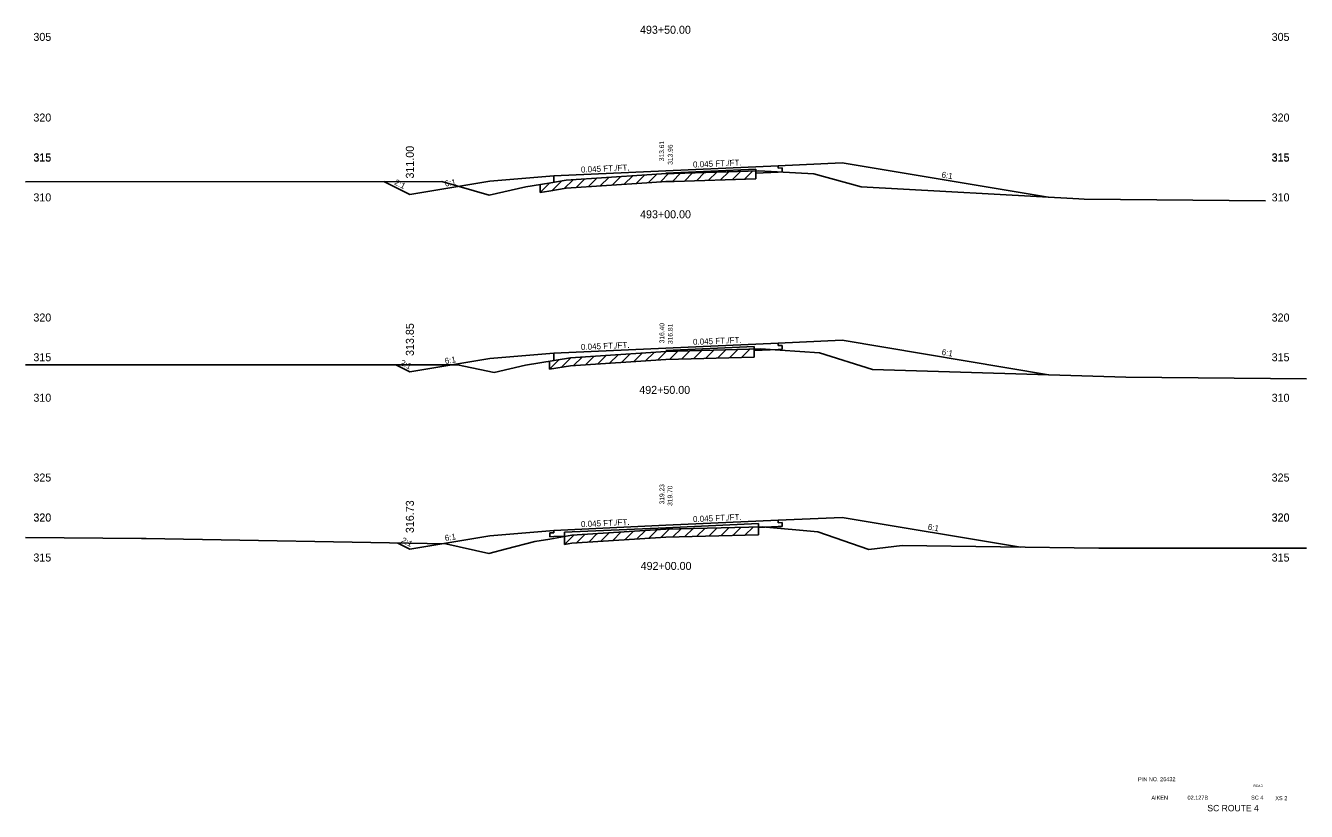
# Model space of a CAD drawing. Extents: x 883 to 1160, y 1002 to 4323.
# Drawn here: x 1000 to 1160, y 1214 to 1312.1 of the extents above; entities that cross this region are included whole.
import ezdxf

# ---------------------------------------------------------------- set-up
doc = ezdxf.new("R2010")
doc.units = 0
for name, color, linetype in [('Level 1', 7, 'Continuous'), ('Level 10', 7, 'Continuous'), ('Level 11', 7, 'Continuous'), ('Level 12', 7, 'Continuous'), ('Level 3', 7, 'Continuous'), ('Level 32', 7, 'Continuous'), ('Level 33', 7, 'Continuous'), ('Level 53', 7, 'Continuous'), ('Level 59', 7, 'Continuous'), ('Level 6', 7, 'Continuous'), ('Level 60', 7, 'Continuous'), ('Level 61', 7, 'Continuous'), ('Level 7', 7, 'Continuous')]:
    doc.layers.add(name, color=color, linetype=linetype)

msp = doc.modelspace()

# ---------------------------------------------------------------- linework, layer by layer
at = {"layer": 'Level 11'}
for p, q in [((1094, 1294.29), (1094, 1294.59)), ((1066, 1292.55), (1066, 1293.33)), ((1094.5, 1294.32), (1094, 1294.29)), ((1094, 1293.81), (1094.5, 1293.84)), ((1094.5, 1293.84), (1094.5, 1294.32)), ((1094, 1272.14), (1094, 1272.44)), ((1094.5, 1272.16), (1094, 1272.14)), ((1094.5, 1271.68), (1094.5, 1272.16)), ((1066, 1270.27), (1066, 1271.18)), ((1094, 1271.66), (1094.5, 1271.68)), ((1094, 1250.03), (1094, 1250.33)), ((1094.5, 1250.05), (1094, 1250.03)), ((1094.5, 1249.57), (1094.5, 1250.05)), ((1066, 1248.77), (1065.5, 1248.75)), ((1065.5, 1248.75), (1065.5, 1248.27)), ((1065.5, 1248.27), (1066, 1248.29)), ((1066, 1249.07), (1066, 1248.77)), ((1094, 1249.55), (1094.5, 1249.57))]:
    msp.add_line(p, q, dxfattribs=at)
at = {"layer": 'Level 12'}
for p, q in [((1091.21, 1293.96), (1091.21, 1293.69)), ((1091.21, 1293.69), (1094, 1293.81)), ((1091, 1271.7), (1091, 1271.53)), ((1091, 1271.53), (1094, 1271.66)), ((1067.34, 1248.35), (1066, 1248.29)), ((1067.34, 1248.32), (1067.34, 1248.35)), ((1091.56, 1249.44), (1094, 1249.55)), ((1091.56, 1249.51), (1091.56, 1249.44))]:
    msp.add_line(p, q, dxfattribs=at)
at = {"layer": 'Level 53'}
for p, q in [((1080, 1293.66), (1091.21, 1294.17)), ((1091.21, 1294.17), (1091.21, 1293.96)), ((1080, 1271.51), (1091, 1272.01)), ((1091, 1272.01), (1091, 1271.7)), ((1080, 1249.4), (1091.56, 1249.92)), ((1091.56, 1249.92), (1091.56, 1249.51)), ((1080, 1249.4), (1067.34, 1248.83)), ((1067.34, 1248.83), (1067.34, 1248.32))]:
    msp.add_line(p, q, dxfattribs=at)
at = {"layer": 'Level 59'}
for p, q in [((1080, 1293.96), (1094, 1294.59)), ((1066, 1293.33), (1080, 1293.96)), ((1080, 1271.81), (1094, 1272.44)), ((1066, 1271.18), (1080, 1271.81)), ((1066, 1249.07), (1080, 1249.7)), ((1080, 1249.7), (1094, 1250.33))]:
    msp.add_line(p, q, dxfattribs=at)
at = {"layer": 'Level 6'}
for p, q in [((1094, 1294.59), (1102, 1294.95)), ((1058, 1292.67), (1066, 1293.33)), ((1094, 1272.44), (1102, 1272.8)), ((1058, 1270.52), (1066, 1271.18)), ((1094, 1250.33), (1102, 1250.69)), ((1058, 1248.4), (1066, 1249.07))]:
    msp.add_line(p, q, dxfattribs=at)
at = {"layer": 'Level 60'}
for p, q in [((1067.54, 1292.8), (1077.61, 1293.47)), ((1077.61, 1293.47), (1079.44, 1293.6)), ((1079.44, 1293.6), (1080, 1293.62)), ((1080, 1293.62), (1081, 1293.65)), ((1081, 1293.65), (1091.58, 1293.98)), ((1091.58, 1293.98), (1098.48, 1293.59)), ((1098.48, 1293.59), (1104.37, 1291.95)), ((1000, 1292.61), (1052, 1292.63)), ((1052, 1292.63), (1057.92, 1290.94)), ((1057.92, 1290.94), (1062.51, 1291.98)), ((1062.51, 1291.98), (1065.37, 1292.44)), ((1065.37, 1292.44), (1067.54, 1292.8)), ((1104.37, 1291.95), (1131.56, 1290.45)), ((1131.56, 1290.45), (1132.26, 1290.43)), ((1132.26, 1290.43), (1154.9, 1290.2)), ((1064.22, 1269.98), (1068.06, 1270.61)), ((1068.06, 1270.61), (1080, 1271.4)), ((1080, 1271.4), (1091.82, 1271.72)), ((1091.82, 1271.72), (1099.16, 1271.23)), ((1099.16, 1271.23), (1105.81, 1269.17)), ((1000, 1269.76), (1050.87, 1269.72)), ((1050.87, 1269.72), (1053.96, 1269.72)), ((1053.96, 1269.72), (1058.54, 1268.8)), ((1058.54, 1268.8), (1062.44, 1269.68)), ((1062.44, 1269.68), (1064.22, 1269.98)), ((1105.81, 1269.17), (1137.43, 1268.22)), ((1137.43, 1268.22), (1160, 1268)), ((1000, 1248.2), (1014.49, 1248.05)), ((1014.49, 1248.05), (1015.07, 1248.05)), ((1015.07, 1248.05), (1052.49, 1247.39)), ((1065.49, 1247.99), (1068.24, 1248.48)), ((1068.24, 1248.48), (1080, 1249.23)), ((1080, 1249.23), (1092.05, 1249.52)), ((1092.05, 1249.52), (1098.96, 1248.9)), ((1098.96, 1248.9), (1105.34, 1246.69)), ((1052.49, 1247.39), (1057.87, 1246.2)), ((1057.87, 1246.2), (1060.09, 1246.76)), ((1060.09, 1246.76), (1063.63, 1247.66)), ((1063.63, 1247.66), (1065.49, 1247.99)), ((1105.34, 1246.69), (1109.5, 1247.17)), ((1109.5, 1247.17), (1134.07, 1246.84)), ((1134.07, 1246.84), (1140.73, 1246.84)), ((1140.73, 1246.84), (1160, 1246.83))]:
    msp.add_line(p, q, dxfattribs=at)
at = {"layer": 'Level 61'}
for p, q in [((1068.39, 1292.85), (1067.29, 1291.76)), ((1069.87, 1292.95), (1068.79, 1291.88)), ((1071.37, 1293.05), (1070.29, 1291.98)), ((1072.87, 1293.15), (1071.79, 1292.08)), ((1074.37, 1293.26), (1073.29, 1292.18)), ((1075.87, 1293.36), (1074.79, 1292.28)), ((1077.37, 1293.46), (1076.29, 1292.39)), ((1078.87, 1293.56), (1077.8, 1292.49)), ((1080.33, 1293.63), (1079.3, 1292.59)), ((1081.83, 1293.67), (1080.8, 1292.64)), ((1081, 1292.65), (1091.21, 1292.96)), ((1083.33, 1293.72), (1082.3, 1292.69)), ((1084.83, 1293.77), (1083.8, 1292.73)), ((1086.33, 1293.81), (1085.3, 1292.78)), ((1087.83, 1293.86), (1086.8, 1292.83)), ((1089.33, 1293.91), (1088.3, 1292.87)), ((1090.83, 1293.95), (1089.8, 1292.92)), ((1091.21, 1292.96), (1091.21, 1293.96)), ((1065.49, 1292.46), (1064.29, 1291.27)), ((1064.29, 1292.27), (1064.29, 1291.27)), ((1064.29, 1291.27), (1065.37, 1291.44)), ((1065.37, 1291.44), (1067.54, 1291.8)), ((1066.99, 1292.71), (1065.79, 1291.51)), ((1067.54, 1291.8), (1077.61, 1292.47)), ((1077.61, 1292.47), (1079.44, 1292.6)), ((1079.44, 1292.6), (1080, 1292.62)), ((1080, 1292.62), (1081, 1292.65)), ((1068.13, 1270.62), (1066.94, 1269.43)), ((1069.51, 1270.71), (1068.44, 1269.64)), ((1071.01, 1270.81), (1069.94, 1269.74)), ((1072.51, 1270.91), (1071.44, 1269.84)), ((1074.01, 1271), (1072.94, 1269.93)), ((1075.51, 1271.1), (1074.44, 1270.03)), ((1077.01, 1271.2), (1075.94, 1270.13)), ((1078.51, 1271.3), (1077.44, 1270.23)), ((1080.01, 1271.4), (1078.94, 1270.33)), ((1080, 1270.4), (1091, 1270.7)), ((1081.47, 1271.44), (1080.44, 1270.41)), ((1082.97, 1271.48), (1081.94, 1270.45)), ((1084.47, 1271.52), (1083.44, 1270.49)), ((1085.97, 1271.56), (1084.94, 1270.53)), ((1087.47, 1271.6), (1086.45, 1270.57)), ((1088.97, 1271.64), (1087.95, 1270.61)), ((1090.48, 1271.68), (1089.45, 1270.65)), ((1091, 1270.7), (1091, 1271.7)), ((1066.63, 1270.38), (1065.44, 1269.18)), ((1065.44, 1270.18), (1065.44, 1269.18)), ((1065.44, 1269.18), (1068.06, 1269.61)), ((1068.06, 1269.61), (1080, 1270.4)), ((1068.52, 1248.5), (1067.34, 1247.32)), ((1067.34, 1248.32), (1067.34, 1247.32)), ((1068.24, 1247.48), (1080, 1248.23)), ((1069.91, 1248.59), (1068.84, 1247.52)), ((1071.41, 1248.68), (1070.34, 1247.61)), ((1072.91, 1248.78), (1071.84, 1247.71)), ((1074.42, 1248.88), (1073.35, 1247.81)), ((1075.92, 1248.97), (1074.85, 1247.9)), ((1077.42, 1249.07), (1076.35, 1248)), ((1078.92, 1249.16), (1077.85, 1248.09)), ((1080.4, 1249.24), (1079.35, 1248.19)), ((1080, 1248.23), (1091.56, 1248.51)), ((1081.88, 1249.28), (1080.85, 1248.25)), ((1083.38, 1249.31), (1082.36, 1248.29)), ((1084.88, 1249.35), (1083.86, 1248.33)), ((1086.38, 1249.39), (1085.36, 1248.36)), ((1087.89, 1249.42), (1086.86, 1248.4)), ((1089.39, 1249.46), (1088.36, 1248.43)), ((1090.89, 1249.49), (1089.86, 1248.47)), ((1091.56, 1248.51), (1091.56, 1249.51)), ((1067.34, 1247.32), (1068.24, 1247.48))]:
    msp.add_line(p, q, dxfattribs=at)
at = {"layer": 'Level 7'}
for p, q in [((1102, 1294.95), (1127.73, 1290.67)), ((1044.74, 1292.63), (1048, 1291)), ((1048, 1291), (1058, 1292.67)), ((1102, 1272.8), (1127.77, 1268.51)), ((1048, 1268.85), (1058, 1270.52)), ((1046.25, 1269.72), (1048, 1268.85)), ((1102, 1250.69), (1124.3, 1246.97)), ((1048, 1246.73), (1058, 1248.4)), ((1046.48, 1247.49), (1048, 1246.73))]:
    msp.add_line(p, q, dxfattribs=at)

# ---------------------------------------------------------------- texts
at = {"layer": 'Level 1'}
for s, height, p in [('493+50.00', 1, (1076.75, 1311.08)), ('493+00.00', 1, (1076.76, 1288.04)), ('492+50.00', 1, (1076.66, 1266.11)), ('492+00.00', 1, (1076.83, 1244.13)), ('PIN NO. 26432', 0.5, (1138.97, 1217.75)), ('AIKEN', 0.5, (1140.64, 1215.44)), ('02.127B', 0.5, (1145.15, 1215.44)), ('SC ROUTE 4', 0.8, (1147.63, 1213.99)), ('SC 4', 0.5, (1153.09, 1215.44)), ('XS 2', 0.5, (1156.12, 1215.38))]:
    msp.add_text(s, height=height, dxfattribs=at).set_placement(p)
at = {"layer": 'Level 10'}
for s, p in [('313.61', (1079.76, 1295.17)), ('316.40', (1079.79, 1272.43)), ('319.23', (1079.79, 1252.31))]:
    msp.add_text(s, height=0.6, rotation=90, dxfattribs=at).set_placement(p)
at = {"layer": 'Level 3'}
for s, height, p in [(' 305', 1, (1000.6, 1310.19)), (' 305', 1, (1155.29, 1310.19)), (' 320', 1, (1000.6, 1300.12)), (' 320', 1, (1155.29, 1300.12)), (' 315', 1, (1000.6, 1295.16)), (' 315', 1, (1000.6, 1295.1)), (' 315', 1, (1155.29, 1295.16)), (' 315', 1, (1155.29, 1295.1)), (' 310', 1, (1000.6, 1290.15)), (' 310', 1, (1155.29, 1290.15)), (' 320', 1, (1000.6, 1275.15)), (' 320', 1, (1155.29, 1275.15)), (' 315', 1, (1000.6, 1270.19)), (' 315', 1, (1155.29, 1270.19)), (' 310', 1, (1000.6, 1265.13)), (' 310', 1, (1155.29, 1265.13)), (' 325', 1, (1000.6, 1255.17)), (' 325', 1, (1155.29, 1255.17)), (' 320', 1, (1000.6, 1250.19)), (' 320', 1, (1155.29, 1250.19)), (' 320', 1, (1000.6, 1250.16)), (' 320', 1, (1155.29, 1250.16)), (' 315', 1, (1000.6, 1245.18)), (' 315', 1, (1155.29, 1245.18)), ('ROAD', 0.3, (1153.38, 1217.02))]:
    msp.add_text(s, height=height, dxfattribs=at).set_placement(p)
at = {"layer": 'Level 32'}
for s, rotation, p in [('0.045 FT./FT.', 2.5766, (1069.39, 1293.74)), ('0.045 FT./FT.', 2.5766, (1083.39, 1294.37)), ('2:1', 333.435, (1045.98, 1292.29)), ('6:1', 9.4623, (1052.43, 1291.99)), ('6:1', 350.5377, (1114.38, 1293.14)), ('0.045 FT./FT.', 2.5766, (1069.39, 1271.59)), ('0.045 FT./FT.', 2.5766, (1083.39, 1272.22)), ('6:1', 9.4623, (1052.43, 1269.84)), ('6:1', 350.5377, (1114.4, 1270.99)), ('2:1', 333.435, (1046.73, 1269.76)), ('0.045 FT./FT.', 2.5766, (1069.39, 1249.47)), ('0.045 FT./FT.', 2.5766, (1083.39, 1250.1)), ('6:1', 350.5377, (1112.66, 1249.16)), ('2:1', 333.435, (1046.85, 1247.59)), ('6:1', 9.4623, (1052.43, 1247.73))]:
    msp.add_text(s, height=0.75, rotation=rotation, dxfattribs=at).set_placement(p)
at = {"layer": 'Level 33'}
for s, p in [('311.00', (1048.5, 1293)), ('313.85', (1048.5, 1270.85)), ('316.73', (1048.5, 1248.73))]:
    msp.add_text(s, height=1, rotation=90, dxfattribs=at).set_placement(p)
at = {"layer": 'Level 59'}
for s, p in [(' 313.96', (1080.83, 1294.49)), (' 316.81', (1080.84, 1272.11)), (' 319.70', (1080.8, 1251.9))]:
    msp.add_text(s, height=0.6, rotation=90, dxfattribs=at).set_placement(p)

doc.saveas('drawing.dxf')
